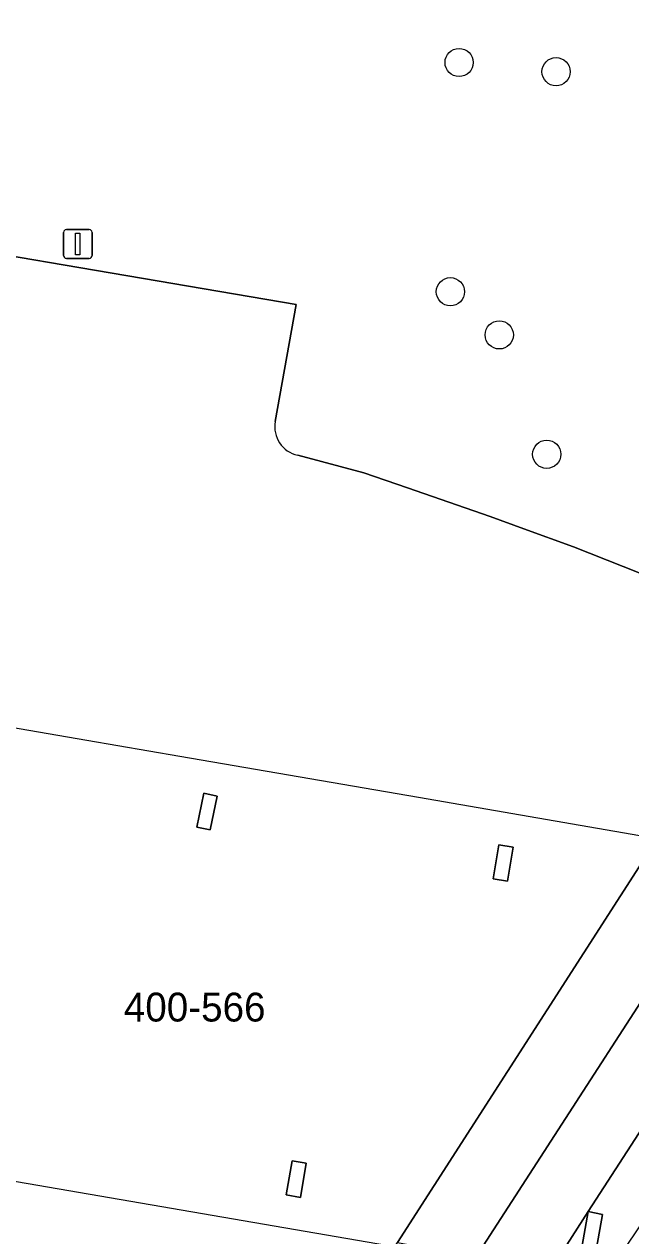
# Model space of a CAD drawing. Extents: x 161258 to 161838, y 380833 to 381727.
# Drawn here: x 161565.99 to 161587, y 381007.58 to 381049.56 of the extents above; entities that cross this region are included whole.
import ezdxf

# ---------------------------------------------------------------- set-up
doc = ezdxf.new("R2010")
doc.units = 0
for name, color, linetype in [('IMGEO_Berm_open', 7, 'Continuous'), ('IMGEO_Boom', 7, 'Continuous'), ('IMGEO_Erf', 7, 'Continuous'), ('IMGEO_Fietspad_gesloten', 7, 'Continuous'), ('IMGEO_Groenvoorziening', 7, 'Continuous'), ('IMGEO_Lichtmast', 7, 'Continuous'), ('IMGEO_Pand', 7, 'Continuous'), ('IMGEO_Pand_nummerreeks', 7, 'Continuous'), ('IMGEO_Pand_overbouw', 7, 'Continuous'), ('IMGEO_Voetpad_open', 7, 'Continuous')]:
    doc.layers.add(name, color=color, linetype=linetype)

msp = doc.modelspace()

# ---------------------------------------------------------------- linework, layer by layer
at = {"layer": 'IMGEO_Berm_open'}
for points in [[(161595.323, 381019.942), (161593.225, 381020.303), (161585.527, 381008.419), (161584.233, 381006.393), (161586.08, 381006.075), (161589.117, 381010.568), (161589.079, 381010.603)], [(161585.527, 381008.419), (161586.016, 381008.314), (161585.807, 381007.147), (161585.315, 381007.235)]]:
    msp.add_lwpolyline(points, close=True, dxfattribs=at)
at = {"layer": 'IMGEO_Boom'}
for centre in [(161581.056, 381048.23), (161584.412, 381047.912), (161580.754, 381040.286), (161582.445, 381038.792), (161584.09, 381034.654)]:
    msp.add_circle(centre, 0.489, dxfattribs=at)
at = {"layer": 'IMGEO_Erf'}
for points in [[(161574.684, 381035.789), (161575.416, 381039.839), (161557.769, 381042.844), (161555.301, 381043.416), (161552.686, 381043.703), (161552.507, 381042.581), (161532.057, 381064.493), (161518.689, 381078.697), (161503.451, 381063.795), (161487.567, 381052.529)], [(161576.218, 381003.146), (161578.828, 381007.201), (161578.923, 381007.348), (161587.915, 381021.334), (161589.389, 381023.626), (161592.569, 381028.461), (161585.018, 381031.447), (161583.298, 381032.072), (161582.135, 381032.494), (161579.268, 381033.49), (161577.753, 381034.017), (161575.464, 381034.622)]]:
    msp.add_lwpolyline(points, dxfattribs=at)
for points in [[(161572.219, 381022.911), (161572.681, 381022.813), (161572.431, 381021.639), (161571.969, 381021.738)], [(161582.436, 381021.128), (161582.931, 381021.045), (161582.732, 381019.861), (161582.237, 381019.944)], [(161575.272, 381010.173), (161575.762, 381010.088), (161575.557, 381008.906), (161575.068, 381008.991)]]:
    msp.add_lwpolyline(points, close=True, dxfattribs=at)
msp.add_arc((161575.684, 381035.613), 1.016, 170.0459, 257.4701, dxfattribs=at)
at = {"layer": 'IMGEO_Fietspad_gesloten'}
for points in [[(161595.079, 381027.823), (161594.29, 381026.415), (161590.696, 381020.856), (161581.633, 381006.84), (161581.562, 381006.731), (161578.938, 381002.688), (161504.207, 380887.394), (161498.991, 380879.345)], [(161550.334, 380954.192), (161560.289, 380969.446), (161563.567, 380974.533), (161571.517, 380986.803), (161573.681, 380990.142), (161579.462, 380999.064), (161581.528, 381002.238), (161584.162, 381006.283), (161584.233, 381006.393), (161585.527, 381008.419), (161593.225, 381020.303), (161593.263, 381020.355), (161593.301, 381020.408)]]:
    msp.add_lwpolyline(points, dxfattribs=at)
at = {"layer": 'IMGEO_Groenvoorziening'}
for points in [[(161572.576, 381088.391), (161571.908, 381087.238), (161571.207, 381085.553), (161579.078, 381083.384), (161581.811, 381066.186), (161579.095, 381065.701), (161576.454, 381065.801), (161572.748, 381066.382), (161571.504, 381067.244), (161569.459, 381069.096), (161567.021, 381071.824), (161566.466, 381073.198), (161557.199, 381048.959), (161555.301, 381043.416), (161557.769, 381042.844), (161575.416, 381039.839), (161574.684, 381035.789)], [(161575.464, 381034.622), (161577.753, 381034.017), (161579.268, 381033.49), (161582.135, 381032.494), (161583.298, 381032.072), (161585.018, 381031.447), (161592.569, 381028.461)]]:
    msp.add_lwpolyline(points, dxfattribs=at)
msp.add_arc((161575.684, 381035.613), 1.016, 170.0459, 257.4701, dxfattribs=at)
at = {"layer": 'IMGEO_Lichtmast'}
for p, q in [((161567.355, 381041.541), (161567.355, 381042.341)), ((161567.355, 381042.341), (161567.355, 381041.541)), ((161567.455, 381042.441), (161568.245, 381042.441)), ((161568.245, 381042.441), (161567.455, 381042.441)), ((161568.345, 381042.341), (161568.345, 381041.541)), ((161568.345, 381041.541), (161568.345, 381042.341)), ((161568.245, 381041.441), (161567.455, 381041.441)), ((161567.455, 381041.441), (161568.245, 381041.441))]:
    msp.add_line(p, q, dxfattribs=at)
msp.add_lwpolyline([(161567.775, 381042.316), (161567.925, 381042.316), (161567.925, 381041.566), (161567.775, 381041.566), (161567.775, 381042.316)], dxfattribs=at)
for centre, start, end in [((161567.455, 381042.341), 90, 180), ((161567.455, 381042.341), 90, 180), ((161568.245, 381042.341), 0, 90), ((161568.245, 381042.341), 360, 90), ((161567.455, 381041.541), 180, 270), ((161567.455, 381041.541), 180, 270), ((161568.245, 381041.541), 270, 0), ((161568.245, 381041.541), 270, 0)]:
    msp.add_arc(centre, 0.1, start, end, dxfattribs=at)
at = {"layer": 'IMGEO_Pand'}
for points in [[(161572.431, 381021.639), (161572.681, 381022.813), (161572.219, 381022.911), (161571.969, 381021.738)], [(161582.732, 381019.861), (161582.931, 381021.045), (161582.436, 381021.128), (161582.237, 381019.944)], [(161575.557, 381008.906), (161575.762, 381010.088), (161575.272, 381010.173), (161575.068, 381008.991)], [(161585.527, 381008.419), (161585.315, 381007.235), (161585.807, 381007.147), (161586.016, 381008.314)]]:
    msp.add_lwpolyline(points, close=True, dxfattribs=at)
at = {"layer": 'IMGEO_Pand_overbouw'}
for points in [[(161630.098, 381007.334), (161631.061, 381012.91), (161638.251, 381011.67), (161638.42, 381012.654), (161599.744, 381019.301), (161595.349, 381020.056), (161587.915, 381021.334), (161579.647, 381022.757), (161571.38, 381024.181), (161568.164, 381024.732), (161546.929, 381028.397), (161543.554, 381028.979), (161529.957, 381031.314), (161529.713, 381031.356), (161529.469, 381031.398), (161494.957, 381037.336)], [(161492.214, 381022.109), (161536.152, 381014.547), (161539.612, 381013.952), (161544.314, 381013.143), (161580.012, 381006.998)]]:
    msp.add_lwpolyline(points, dxfattribs=at)
at = {"layer": 'IMGEO_Voetpad_open'}
msp.add_lwpolyline([(161578.923, 381007.348), (161581.633, 381006.84), (161590.696, 381020.856), (161590.254, 381020.932), (161587.915, 381021.334)], close=True, dxfattribs=at)

# ---------------------------------------------------------------- texts
at = {"layer": 'IMGEO_Pand_nummerreeks'}
msp.add_text('400-566', height=1, dxfattribs=at).set_placement((161569.443, 381015))

doc.saveas('drawing.dxf')
